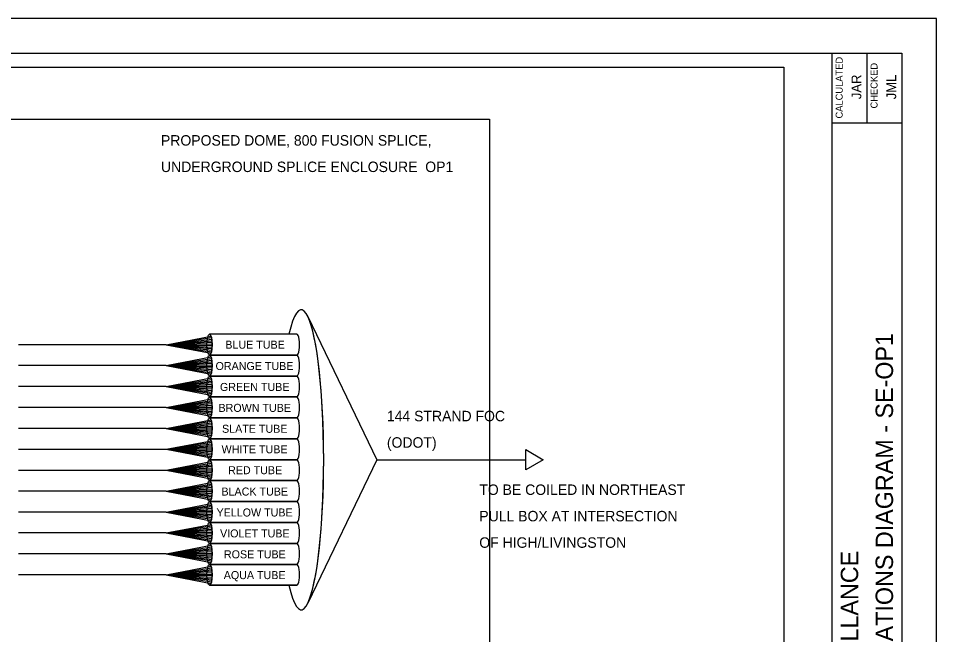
# Model space of a CAD drawing. Extents: x 1805893 to 1833564, y 708898 to 716199.
# Drawn here: x 1831739.1 to 1832002.5, y 716022.7 to 716199.4 of the extents above; entities that cross this region are included whole.
import ezdxf

# ---------------------------------------------------------------- set-up
doc = ezdxf.new("R2010")
doc.units = 0
for name, color, linetype in [('BR_P_Sub_Hidden', 7, 'Continuous'), ('SH_Border', 7, 'Continuous'), ('SH_Cut_Line', 7, 'Continuous'), ('SH_Data', 7, 'Continuous'), ('SH_Text', 7, 'Continuous')]:
    doc.layers.add(name, color=color, linetype=linetype)

msp = doc.modelspace()

# ---------------------------------------------------------------- linework, layer by layer
at = {"layer": 'BR_P_Sub_Hidden'}
for points in [[(1831500.15, 716185.43), (1831958.68, 716185.43), (1831958.68, 715774.93), (1831500.15, 715774.93)], [(1831599.93, 716170.47), (1831874.29, 716170.47), (1831874.29, 715827.21), (1831599.93, 715827.21)]]:
    msp.add_lwpolyline(points, close=True, dxfattribs=at)
at = {"layer": 'SH_Border'}
for p, q in [((1831972.49, 715769.4), (1831972.49, 716189.4)), ((1831982.49, 716189.4), (1831982.49, 716169.4)), ((1831972.49, 716169.4), (1831992.49, 716169.4))]:
    msp.add_line(p, q, dxfattribs=at)
msp.add_lwpolyline([(1831362.49, 716189.4), (1831992.49, 716189.4), (1831992.49, 715769.4), (1831362.49, 715769.4)], close=True, dxfattribs=at)
at = {"layer": 'SH_Cut_Line'}
msp.add_lwpolyline([(1831322.49, 715759.4), (1832002.49, 715759.4), (1832002.49, 716199.4), (1831322.49, 716199.4)], close=True, dxfattribs=at)
at = {"layer": 'SH_Data'}
for p, q in [((1831781.55, 716105.83), (1831794.39, 716108.3)), ((1831819.02, 716108.83), (1831793.97, 716108.83)), ((1831819.02, 716108.83), (1831793.97, 716108.83)), ((1831781.55, 716105.83), (1831739.14, 716105.83)), ((1831781.55, 716105.83), (1831794.52, 716107.85)), ((1831781.55, 716105.83), (1831794.6, 716107.4)), ((1831781.55, 716105.83), (1831794.66, 716106.95)), ((1831781.55, 716105.83), (1831794.7, 716106.5)), ((1831781.55, 716105.83), (1831794.71, 716106.05)), ((1831781.55, 716105.83), (1831794.66, 716104.7)), ((1831781.55, 716105.83), (1831794.6, 716104.25)), ((1831781.55, 716105.83), (1831794.52, 716103.8)), ((1831781.55, 716105.83), (1831794.39, 716103.35)), ((1831781.55, 716105.83), (1831794.7, 716105.15)), ((1831781.55, 716105.83), (1831794.71, 716105.6)), ((1831781.55, 716099.83), (1831794.39, 716102.3)), ((1831781.55, 716099.83), (1831794.52, 716101.85)), ((1831781.55, 716099.83), (1831794.6, 716101.4)), ((1831781.55, 716099.83), (1831794.66, 716100.95)), ((1831781.55, 716099.83), (1831794.7, 716100.5)), ((1831793.97, 716102.83), (1831819.02, 716102.83)), ((1831819.02, 716102.83), (1831793.97, 716102.83)), ((1831781.55, 716099.83), (1831739.14, 716099.83)), ((1831781.55, 716099.83), (1831794.71, 716100.05)), ((1831781.55, 716099.83), (1831794.66, 716098.7)), ((1831781.55, 716099.83), (1831794.6, 716098.25)), ((1831781.55, 716099.83), (1831794.52, 716097.8)), ((1831781.55, 716099.83), (1831794.39, 716097.35)), ((1831781.55, 716099.83), (1831794.7, 716099.15)), ((1831781.55, 716099.83), (1831794.71, 716099.6)), ((1831781.55, 716093.83), (1831794.39, 716096.3)), ((1831781.55, 716093.83), (1831794.52, 716095.85)), ((1831781.55, 716093.83), (1831794.6, 716095.4)), ((1831819.02, 716096.83), (1831793.97, 716096.83)), ((1831793.97, 716096.83), (1831819.02, 716096.83)), ((1831781.55, 716093.83), (1831739.14, 716093.83)), ((1831781.55, 716093.83), (1831794.66, 716094.95)), ((1831781.55, 716093.83), (1831794.7, 716094.5)), ((1831781.55, 716093.83), (1831794.71, 716094.05)), ((1831781.55, 716093.83), (1831794.66, 716092.7)), ((1831781.55, 716093.83), (1831794.6, 716092.25)), ((1831781.55, 716093.83), (1831794.52, 716091.8)), ((1831781.55, 716093.83), (1831794.39, 716091.35)), ((1831781.55, 716093.83), (1831794.7, 716093.15)), ((1831781.55, 716093.83), (1831794.71, 716093.6)), ((1831781.55, 716087.83), (1831794.39, 716090.3)), ((1831781.55, 716087.83), (1831794.52, 716089.85)), ((1831793.97, 716090.83), (1831819.02, 716090.83)), ((1831819.02, 716090.83), (1831793.97, 716090.83)), ((1831781.55, 716087.83), (1831739.14, 716087.83)), ((1831781.55, 716087.83), (1831794.6, 716089.4)), ((1831781.55, 716087.83), (1831794.66, 716088.95)), ((1831781.55, 716087.83), (1831794.7, 716088.5)), ((1831781.55, 716087.83), (1831794.71, 716088.05)), ((1831781.55, 716087.83), (1831794.66, 716086.7)), ((1831781.55, 716087.83), (1831794.6, 716086.25)), ((1831781.55, 716087.83), (1831794.52, 716085.8)), ((1831781.55, 716087.83), (1831794.39, 716085.35)), ((1831781.55, 716087.83), (1831794.7, 716087.15)), ((1831781.55, 716087.83), (1831794.71, 716087.6)), ((1831793.97, 716084.83), (1831819.02, 716084.83)), ((1831819.02, 716084.83), (1831793.97, 716084.83)), ((1831781.55, 716081.83), (1831739.14, 716081.83)), ((1831781.55, 716081.83), (1831794.39, 716084.3)), ((1831781.55, 716081.83), (1831794.52, 716083.85)), ((1831781.55, 716081.83), (1831794.6, 716083.4)), ((1831781.55, 716081.83), (1831794.66, 716082.95)), ((1831781.55, 716081.83), (1831794.7, 716082.5)), ((1831781.55, 716081.83), (1831794.71, 716082.05)), ((1831781.55, 716081.83), (1831794.66, 716080.7)), ((1831781.55, 716081.83), (1831794.6, 716080.25)), ((1831781.55, 716081.83), (1831794.52, 716079.8)), ((1831781.55, 716081.83), (1831794.39, 716079.35)), ((1831781.55, 716081.83), (1831794.7, 716081.15)), ((1831781.55, 716081.83), (1831794.71, 716081.6)), ((1831781.55, 716075.83), (1831794.39, 716078.3)), ((1831781.55, 716075.83), (1831794.52, 716077.85)), ((1831781.55, 716075.83), (1831794.6, 716077.4)), ((1831781.55, 716075.83), (1831794.66, 716076.95)), ((1831793.97, 716078.83), (1831819.02, 716078.83)), ((1831819.02, 716078.83), (1831793.97, 716078.83)), ((1831781.55, 716075.8), (1831739.14, 716075.78)), ((1831781.55, 716075.83), (1831794.7, 716076.5)), ((1831781.55, 716075.83), (1831794.71, 716076.05)), ((1831781.55, 716075.83), (1831794.66, 716074.7)), ((1831781.55, 716075.83), (1831794.6, 716074.25)), ((1831781.55, 716075.83), (1831794.52, 716073.8)), ((1831781.55, 716075.83), (1831794.39, 716073.35)), ((1831781.55, 716075.83), (1831794.7, 716075.15)), ((1831781.55, 716075.83), (1831794.71, 716075.6)), ((1831884.64, 716069.93), (1831884.64, 716075.73)), ((1831884.64, 716075.73), (1831889.66, 716072.83)), ((1831781.55, 716069.83), (1831794.39, 716072.3)), ((1831781.55, 716069.83), (1831794.52, 716071.85)), ((1831781.55, 716069.83), (1831794.6, 716071.4)), ((1831793.97, 716072.83), (1831819.02, 716072.83)), ((1831819.02, 716072.83), (1831793.97, 716072.83)), ((1831841.91, 716072.83), (1831884.64, 716072.83)), ((1831889.66, 716072.83), (1831884.64, 716069.93)), ((1831739.14, 716069.83), (1831781.55, 716069.83)), ((1831781.55, 716069.83), (1831794.66, 716070.95)), ((1831781.55, 716069.83), (1831794.7, 716070.5)), ((1831781.55, 716069.83), (1831794.71, 716070.05)), ((1831781.55, 716069.83), (1831794.66, 716068.7)), ((1831781.55, 716069.83), (1831794.6, 716068.25)), ((1831781.55, 716069.83), (1831794.52, 716067.8)), ((1831781.55, 716069.83), (1831794.39, 716067.35)), ((1831781.55, 716069.83), (1831794.7, 716069.15)), ((1831781.55, 716069.83), (1831794.71, 716069.6)), ((1831781.55, 716063.83), (1831794.39, 716066.3)), ((1831793.97, 716066.83), (1831819.02, 716066.83)), ((1831819.02, 716066.83), (1831793.97, 716066.83)), ((1831781.55, 716063.83), (1831739.14, 716063.83)), ((1831781.55, 716063.83), (1831794.52, 716065.85)), ((1831781.55, 716063.83), (1831794.6, 716065.4)), ((1831781.55, 716063.83), (1831794.66, 716064.95)), ((1831781.55, 716063.83), (1831794.7, 716064.5)), ((1831781.55, 716063.83), (1831794.71, 716064.05)), ((1831781.55, 716063.83), (1831794.66, 716062.7)), ((1831781.55, 716063.83), (1831794.6, 716062.25)), ((1831781.55, 716063.83), (1831794.52, 716061.8)), ((1831781.55, 716063.83), (1831794.39, 716061.35)), ((1831781.55, 716063.83), (1831794.7, 716063.15)), ((1831781.55, 716063.83), (1831794.71, 716063.6)), ((1831819.02, 716060.83), (1831793.97, 716060.83)), ((1831793.97, 716060.83), (1831819.02, 716060.83)), ((1831781.55, 716057.83), (1831794.39, 716060.3)), ((1831781.55, 716057.83), (1831794.52, 716059.85)), ((1831781.55, 716057.83), (1831794.6, 716059.4)), ((1831781.55, 716057.83), (1831794.66, 716058.95)), ((1831781.55, 716057.83), (1831794.7, 716058.5)), ((1831781.55, 716057.83), (1831739.14, 716057.83)), ((1831781.55, 716057.83), (1831794.71, 716058.05)), ((1831781.55, 716057.83), (1831794.66, 716056.7)), ((1831781.55, 716057.83), (1831794.6, 716056.25)), ((1831781.55, 716057.83), (1831794.52, 716055.8)), ((1831781.55, 716057.83), (1831794.39, 716055.35)), ((1831781.55, 716057.83), (1831794.7, 716057.15)), ((1831781.55, 716057.83), (1831794.71, 716057.6)), ((1831781.55, 716051.83), (1831794.39, 716054.3)), ((1831781.55, 716051.83), (1831794.52, 716053.85)), ((1831781.55, 716051.83), (1831794.6, 716053.4)), ((1831781.55, 716051.83), (1831794.66, 716052.95)), ((1831793.97, 716054.83), (1831819.02, 716054.83)), ((1831819.02, 716054.83), (1831793.97, 716054.83)), ((1831781.55, 716051.83), (1831739.14, 716051.83)), ((1831781.55, 716051.83), (1831794.7, 716052.5)), ((1831781.55, 716051.83), (1831794.71, 716052.05)), ((1831781.55, 716051.83), (1831794.66, 716050.7)), ((1831781.55, 716051.83), (1831794.6, 716050.25)), ((1831781.55, 716051.83), (1831794.52, 716049.8)), ((1831781.55, 716051.83), (1831794.39, 716049.35)), ((1831781.55, 716051.83), (1831794.7, 716051.15)), ((1831781.55, 716051.83), (1831794.71, 716051.6)), ((1831781.55, 716045.83), (1831794.39, 716048.3)), ((1831781.55, 716045.83), (1831794.52, 716047.85)), ((1831793.97, 716048.83), (1831819.02, 716048.83)), ((1831819.02, 716048.83), (1831793.97, 716048.83)), ((1831781.55, 716045.83), (1831739.14, 716045.83)), ((1831781.55, 716045.83), (1831794.6, 716047.4)), ((1831781.55, 716045.83), (1831794.66, 716046.95)), ((1831781.55, 716045.83), (1831794.7, 716046.5)), ((1831781.55, 716045.83), (1831794.71, 716046.05)), ((1831781.55, 716045.83), (1831794.66, 716044.7)), ((1831781.55, 716045.83), (1831794.6, 716044.25)), ((1831781.55, 716045.83), (1831794.52, 716043.8)), ((1831781.55, 716045.83), (1831794.39, 716043.35)), ((1831781.55, 716045.83), (1831794.7, 716045.15)), ((1831781.55, 716045.83), (1831794.71, 716045.6)), ((1831793.97, 716042.83), (1831819.02, 716042.83)), ((1831819.02, 716042.83), (1831793.97, 716042.83)), ((1831781.55, 716039.8), (1831739.14, 716039.78)), ((1831781.55, 716039.83), (1831794.39, 716042.3)), ((1831781.55, 716039.83), (1831794.52, 716041.85)), ((1831781.55, 716039.83), (1831794.6, 716041.4)), ((1831781.55, 716039.83), (1831794.66, 716040.95)), ((1831781.55, 716039.83), (1831794.7, 716040.5)), ((1831781.55, 716039.83), (1831794.71, 716040.05)), ((1831781.55, 716039.83), (1831794.66, 716038.7)), ((1831781.55, 716039.83), (1831794.6, 716038.25)), ((1831781.55, 716039.83), (1831794.52, 716037.8)), ((1831781.55, 716039.83), (1831794.39, 716037.35)), ((1831781.55, 716039.83), (1831794.7, 716039.15)), ((1831781.55, 716039.83), (1831794.71, 716039.6)), ((1831793.97, 716036.83), (1831819.02, 716036.83)), ((1831819.02, 716036.83), (1831793.97, 716036.83)), ((1831793.97, 716036.83), (1831816.73, 716036.83))]:
    msp.add_line(p, q, dxfattribs=at)
msp.add_lwpolyline([(1831822.18, 716113.93), (1831841.91, 716072.83), (1831822.18, 716031.73)], dxfattribs=at)
msp.add_lwpolyline([(1831822.18, 716113.93), (1831841.91, 716072.83), (1831822.18, 716031.73)], dxfattribs=at)
for centre, major_axis, ratio, start_param, end_param in [((1831820.26, 716072.83), (0, -43.05), 0.149566, 5.702888, 10.005075), ((1831820.26, 716072.83), (0, -43.05), 0.149566, 5.702888, 10.005075), ((1831820.26, 716072.83), (0, -43.05), 0.149566, 0.302036, 2.839557), ((1831793.97, 716105.83), (0, -3), 0.25, 0, 3.141593), ((1831819.02, 716105.83), (0, -3), 0.25, 0, 3.141593), ((1831819.02, 716105.83), (0, -3), 0.25, 0, 3.141593), ((1831793.97, 716099.83), (0, -3), 0.25, 0, 3.141593), ((1831819.02, 716099.83), (0, -3), 0.25, 0, 3.141593), ((1831819.02, 716099.83), (0, -3), 0.25, 0, 3.141593), ((1831793.97, 716093.83), (0, -3), 0.25, 0, 3.141593), ((1831819.02, 716093.83), (0, -3), 0.25, 0, 3.141593), ((1831819.02, 716093.83), (0, -3), 0.25, 0, 3.141593), ((1831793.97, 716087.83), (0, -3), 0.25, 0, 3.141593), ((1831819.02, 716087.83), (0, -3), 0.25, 0, 3.141593), ((1831819.02, 716087.83), (0, -3), 0.25, 0, 3.141593), ((1831793.97, 716081.83), (0, -3), 0.25, 0, 3.141593), ((1831819.02, 716081.83), (0, -3), 0.25, 0, 3.141593), ((1831819.02, 716081.83), (0, -3), 0.25, 0, 3.141593), ((1831793.97, 716075.83), (0, -3), 0.25, 0, 3.141593), ((1831819.02, 716075.83), (0, -3), 0.25, 0, 3.141593), ((1831819.02, 716075.83), (0, -3), 0.25, 0, 3.141593), ((1831793.97, 716069.83), (0, -3), 0.25, 0, 3.141593), ((1831819.02, 716069.83), (0, -3), 0.25, 0, 3.141593), ((1831819.02, 716069.83), (0, -3), 0.25, 0, 3.141593), ((1831793.97, 716063.83), (0, -3), 0.25, 0, 3.141593), ((1831819.02, 716063.83), (0, -3), 0.25, 0, 3.141593), ((1831819.02, 716063.83), (0, -3), 0.25, 0, 3.141593), ((1831793.97, 716057.83), (0, -3), 0.25, 0, 3.141593), ((1831819.02, 716057.83), (0, -3), 0.25, 0, 3.141593), ((1831819.02, 716057.83), (0, -3), 0.25, 0, 3.141593), ((1831793.97, 716051.83), (0, -3), 0.25, 0, 3.141593), ((1831819.02, 716051.83), (0, -3), 0.25, 0, 3.141593), ((1831819.02, 716051.83), (0, -3), 0.25, 0, 3.141593), ((1831793.97, 716045.83), (0, -3), 0.25, 0, 3.141593), ((1831819.02, 716045.83), (0, -3), 0.25, 0, 3.141593), ((1831819.02, 716045.83), (0, -3), 0.25, 0, 3.141593), ((1831793.97, 716039.83), (0, -3), 0.25, 0, 3.141593), ((1831819.02, 716039.83), (0, -3), 0.25, 0, 3.141593), ((1831819.02, 716039.83), (0, -3), 0.25, 0, 3.141593)]:
    msp.add_ellipse(centre, major_axis=major_axis, ratio=ratio, start_param=start_param, end_param=end_param, dxfattribs=at)
for centre in [(1831793.97, 716105.83), (1831793.97, 716099.83), (1831793.97, 716093.83), (1831793.97, 716087.83), (1831793.97, 716081.83), (1831793.97, 716075.83), (1831793.97, 716069.83), (1831793.97, 716063.83), (1831793.97, 716057.83), (1831793.97, 716051.83), (1831793.97, 716045.83), (1831793.97, 716039.83)]:
    msp.add_ellipse(centre, major_axis=(0, -3), ratio=0.25, dxfattribs=at)

# ---------------------------------------------------------------- texts
for s, height, rotation, p in [('CALCULATED', 2, 90, (1831975.54, 716170.69)), ('CHECKED', 2, 90, (1831985.54, 716173.56)), ('JAR', 2.8, 90, (1831980.89, 716176.23)), ('JML', 2.8, 90, (1831990.89, 716176.19)), ('PERMANENT ITS PLAN - COMMUNICATIONS DIAGRAM - SE-OP1', 5, 90, (1831989.99, 715903.73)), ('BLUE TUBE', 2.295, 360, (1831798.49, 716104.68)), ('ORANGE TUBE', 2.2947, 360, (1831795.69, 716098.56)), ('GREEN TUBE', 2.295, 360, (1831796.95, 716092.56)), ('BROWN TUBE', 2.295, 360, (1831796.53, 716086.56)), ('144 STRAND FOC', 3, 360, (1831844.83, 716083.86)), ('SLATE TUBE', 2.295, 360, (1831797.55, 716080.56)), ('(ODOT)', 3, 360, (1831844.83, 716076.28)), ('WHITE TUBE', 2.295, 360, (1831797.42, 716074.68)), ('RED TUBE', 2.295, 360, (1831799.29, 716068.68)), ('BLACK TUBE', 2.295, 360, (1831797.38, 716062.56)), ('TO BE COILED IN NORTHEAST', 3, 360, (1831871.33, 716062.74)), ('YELLOW TUBE', 2.2947, 360, (1831795.97, 716056.56)), ('PULL BOX AT INTERSECTION  ', 3, 360, (1831871.33, 716055.16)), ('VIOLET TUBE', 2.2947, 360, (1831796.98, 716050.56)), ('OF HIGH/LIVINGSTON', 3, 360, (1831871.33, 716047.58)), ('ROSE TUBE', 2.295, 360, (1831798.09, 716044.56)), ('TRAFFIC SURVEILLANCE', 5, 90, (1831979.99, 715965.72)), ('AQUA TUBE', 2.295, 360, (1831798.04, 716038.6))]:
    msp.add_text(s, height=height, rotation=rotation, dxfattribs=at).set_placement(p)
at = {"layer": 'SH_Text'}
for s, p in [('PROPOSED DOME, 800 FUSION SPLICE, ', (1831780.04, 716162.91)), ('UNDERGROUND SPLICE ENCLOSURE  OP1', (1831780.04, 716155.33))]:
    msp.add_text(s, height=3, dxfattribs=at).set_placement(p)

doc.saveas('drawing.dxf')
